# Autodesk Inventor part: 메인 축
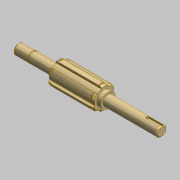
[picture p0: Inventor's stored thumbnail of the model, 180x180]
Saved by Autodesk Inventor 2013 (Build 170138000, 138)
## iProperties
Created: 2015-11
Part Number: 메인 축
Document SubType Name: 모델링
Designer: mdu
Mass: 168.566 g
Surface Area: 72.5108 cm^2
Volume: 21.4461 cm^3
Density: 7.86 g/cm^3
Material: 강철, 연강
변환 표준: STEP AP214IS
파일 이름: C:\Users\SeoGD\Desktop\?쒗뿕\硫붿씤 異?.stp
전처리기: Build: 253, Release: 2010 SP1 - Date: Wed 07/29/2009
전송 단위: 밀리미터
불확실성: 0.01
Author: mdu
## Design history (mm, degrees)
sketch "스케치1"
  geometry: L1 (-69.5, 0)-(69.5, 0); L2 (69.5, 0)-(69.5, 5); L3 (69.5, 5)-(55.5, 5); L4 (55.5, 5)-(55.5, 4.8); L5 (55.5, 4.8)-(54.35, 4.8); L6 (54.35, 4.8)-(54.35, 5); L7 (54.35, 5)-(30.5, 5); L8 (30.5, 5)-(30.5, 9); L9 (30.5, 9)-(-13.5, 9); L10 (-13.5, 9)-(-13.5, 7); L11 (-13.5, 7)-(-17.5, 7); L12 (-17.5, 7)-(-17.5, 5); L13 (-17.5, 5)-(-69.5, 5); L14 (-69.5, 5)-(-69.5, 0); 2 further points
  constraints: 28 end point, 9 parallel, 4 collinear, 2 perpendicular, 1 coincident, 1 horizontal, 1 midpoint
  dimensions: "d2" = 1.15 distance between parallel lines of L6 L4; "d3" = 10 diameter of L3 L1; "d4" = 9.6 diameter of L5 L1; "d6" = 44 distance between parallel lines of L10 L8; "d7" = 4 distance between parallel lines of L12 L10; "d8" = 14 diameter of L11 L1; "d9" = 18 diameter of L9 L1; "d33" = 52 distance from line of L12.end L14; "d37" = 39 distance between parallel lines of L8 L2; "d38" = 14 distance between parallel lines of L2 L4
revolve "회전1" sketch "스케치1" stored, may be unused: angle "d10" = 90 deg
sketch "스케치2"
  geometry: L1 (2.5, 10.712)-(2.5, 8.646); L2 (-2.5, 10.712)-(-2.5, 8.646); A1 r 9 centre (0, 0) between (2.5, 8.646) and (-2.5, 8.646) reference; A2 r 11 centre (0, 0) between (2.5, 10.712) and (-2.5, 10.712); 1 further point
  constraints: 4 end point, 4 point on circle, 2 parallel, 1 centre point, 1 coincident, 1 vertical
  dimensions: "d11" = 22 diameter of A2; "d12" = 5 distance between parallel lines of L1 L2
extrude "돌출1" join sketch "스케치2" stored distance "d13" = 10; taper "d14" = 0 deg
chamfer "모따기1" distance "d15" = 1; stored, may be unused: second distance "d16" = 2, angle "d17" = 45 deg
node "작업 평면1"
node "작업 평면2"
sketch "스케치3"
  geometry: L1 (2.5, 10.712)-(2.5, 10.198); L2 (-2.5, 10.712)-(-2.5, 10.198); A1 r 11 centre (0, 0) between (2.5, 10.712) and (-2.5, 10.712) reference; A2 r 10.5 centre (0, 0) between (2.5, 10.198) and (-2.5, 10.198); 1 further point
  constraints: 4 end point, 2 point on circle, 1 centre point, 1 coincident, 1 parallel, 1 vertical
  dimensions: "d19" = 21 diameter of A2
extrude "돌출2" cut sketch "스케치3" distance "d20" = 1.35; taper "d21" = 0 deg
node "작업 평면3"
sketch "스케치4"
  geometry: L1 (-26, -5)-(-26, 5) reference; L2 (-26, 1.5)-(-12.5, 1.5); L3 (-12.5, -1.5)-(-26, -1.5); A1 r 1.5 centre (-12.5, 0) between (-12.5, -1.5) and (-12.5, 1.5); 2 further points
  constraints: 4 end point, 2 perpendicular, 2 point on circle, 2 point on line, 2 tangent, 1 centre point, 1 horizontal alignment, 1 midpoint
  dimensions: "d25" = 3 distance between parallel lines of L3 L2; "d26" = 15 dimension on A1 L1
extrude "돌출3" cut sketch "스케치4" distance "d27" = 1.8; taper "d28" = 0 deg
chamfer "모따기2" distance "d29" = 1; stored, may be unused: second distance "d30" = 2, angle "d31" = 45 deg
node "솔리드1"
node "솔리드 본체"
node "곡면 본체"
mirror "대칭1"
pattern_circular "원형 패턴1" dims "d23" = 360 deg
node "솔리드2"
other parameters: "d18" = -1.65
